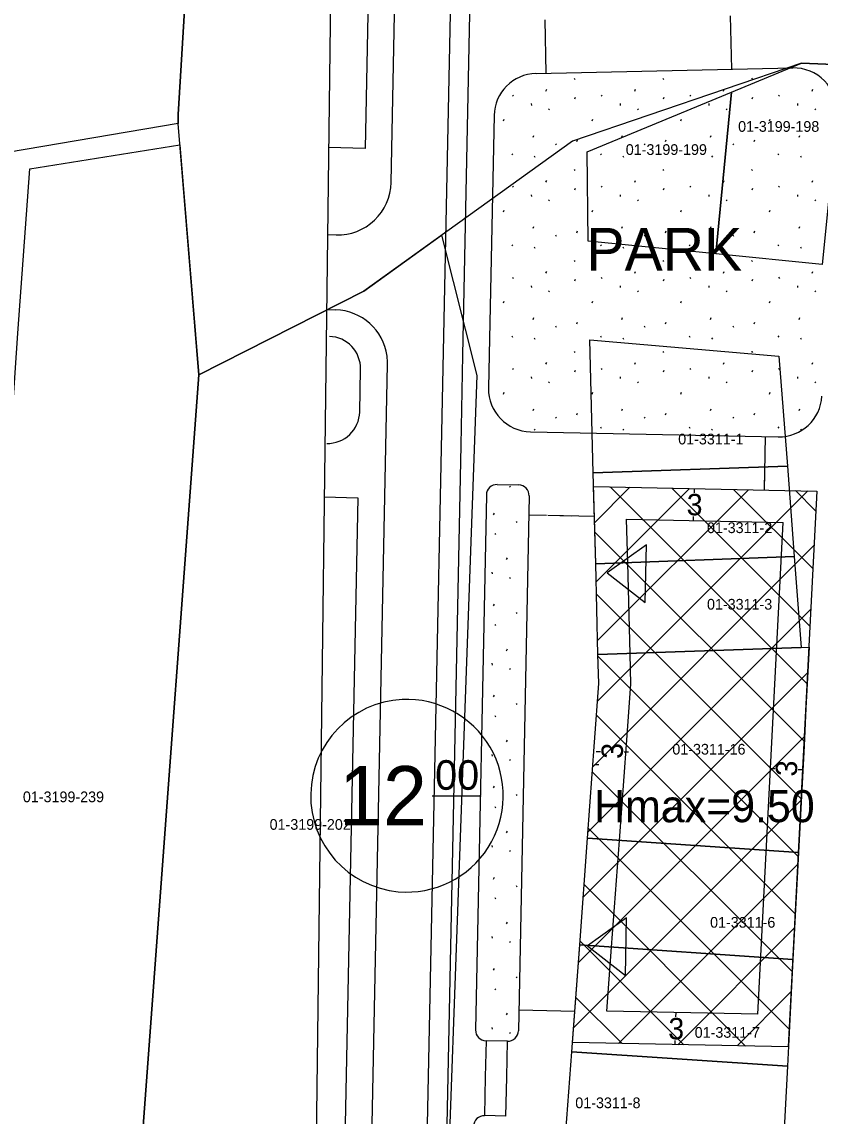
# Model space of a CAD drawing. Extents: x 419396 to 421519, y 4453567 to 4456767.
# Drawn here: x 420396.5 to 420471.1, y 4454516.9 to 4454619.2 of the extents above; entities that cross this region are included whole.
import ezdxf

# ---------------------------------------------------------------- set-up
doc = ezdxf.new("R2010")
doc.units = 0
for name, color, linetype in [('0_KADASTRO', 7, 'Continuous'), ('Level 16', 7, 'Continuous'), ('Level 20', 7, 'Continuous'), ('Level 28', 7, 'Continuous'), ('Level 29', 7, 'Continuous'), ('Level 30', 7, 'Continuous'), ('Level 34', 7, 'Continuous'), ('Level 41', 7, 'Continuous'), ('Level 58', 7, 'Continuous'), ('Level 61', 7, 'Continuous'), ('Level 62', 7, 'Continuous'), ('Level 9', 7, 'Continuous')]:
    doc.layers.add(name, color=color, linetype=linetype)

msp = doc.modelspace()

# ---------------------------------------------------------------- linework, layer by layer
at = {"layer": '0_KADASTRO'}
for points in [[(420411.11, 4454610.55), (420417.99, 4454723.39), (420418.06, 4454727.12), (420520.79, 4454737.14), (420523.08, 4454624.12), (420522.64, 4454620.22), (420521.58, 4454610.83), (420521.56, 4454610.63), (420521.36, 4454610.66), (420513.12, 4454611.66), (420503.2, 4454612.87), (420493.29, 4454614.08), (420489.81, 4454614.5), (420483.17, 4454614.78), (420473.19, 4454615.2), (420469.38, 4454615.35), (420447.99, 4454608.07), (420428.47, 4454594.05), (420413.06, 4454586.21), (420411.13, 4454609.71)], [(420461.37, 4454597.53), (420462.84, 4454612.64), (420469.38, 4454615.35), (420473.19, 4454615.2), (420471.31, 4454596.54)], [(420449.36, 4454607.06), (420462.84, 4454612.64), (420461.37, 4454597.53), (420449.43, 4454598.73)], [(420388.29, 4454473.82), (420396.15, 4454590.13), (420397.27, 4454605.49), (420411.29, 4454607.72), (420413.06, 4454586.21), (420404.4, 4454469.34)], [(420404.4, 4454469.34), (420413.06, 4454586.21), (420428.47, 4454594.05), (420435.75, 4454599.28), (420439.04, 4454586.15), (420434.51, 4454460.97)], [(420449.59, 4454589.48), (420467.28, 4454587.96), (420468.07, 4454577.69), (420449.92, 4454577.07)], [(420449.92, 4454577.07), (420468.07, 4454577.69), (420468.71, 4454569.23), (420450.15, 4454568.56)], [(420450.15, 4454568.56), (420468.71, 4454569.23), (420469.36, 4454560.75), (420450.36, 4454560.07)], [(420449.37, 4454542.91), (420450.04, 4454551.88), (420450.44, 4454557.37), (420450.36, 4454560.07), (420469.36, 4454560.75), (420470.09, 4454560.77), (420469.8, 4454555.06), (420469.63, 4454551.56), (420469.1, 4454541.58)], [(420448.65, 4454532.94), (420449.37, 4454542.91), (420469.1, 4454541.58), (420468.58, 4454531.59)], [(420447.92, 4454522.96), (420448.65, 4454532.94), (420468.58, 4454531.59), (420468.06, 4454521.61)], [(420447.18, 4454512.99), (420447.92, 4454522.96), (420468.06, 4454521.61), (420467.54, 4454511.62)]]:
    msp.add_lwpolyline(points, close=True, dxfattribs=at)
msp.add_lwpolyline([(420372.18, 4454711.5), (420417.99, 4454723.39), (420411.11, 4454610.55), (420411.13, 4454609.71), (420384.14, 4454605.13)], dxfattribs=at)
at = {"layer": 'Level 16'}
for p, q in [((420454.89, 4454570.34), (420451.23, 4454567.72)), ((420454.89, 4454570.34), (420451.23, 4454567.72)), ((420454.78, 4454564.94), (420454.89, 4454570.34)), ((420454.78, 4454564.94), (420454.89, 4454570.34)), ((420451.23, 4454567.72), (420454.78, 4454564.94)), ((420451.23, 4454567.72), (420454.78, 4454564.94)), ((420453.04, 4454535.47), (420449.39, 4454532.84)), ((420453.04, 4454535.47), (420449.39, 4454532.84)), ((420452.94, 4454530.07), (420453.04, 4454535.47)), ((420452.94, 4454530.07), (420453.04, 4454535.47)), ((420449.39, 4454532.84), (420452.94, 4454530.07)), ((420449.39, 4454532.84), (420452.94, 4454530.07))]:
    msp.add_line(p, q, dxfattribs=at)
at = {"layer": 'Level 20'}
for p, q in [((420459.34, 4454575.59), (420459.34, 4454575.19)), ((420459.34, 4454575.59), (420459.34, 4454575.19)), ((420459.34, 4454575.59), (420459.34, 4454575.19)), ((420459.34, 4454575.59), (420459.34, 4454575.19)), ((420453.03, 4454572.72), (420467.67, 4454572.42)), ((420453.14, 4454568.64), (420453.03, 4454572.72)), ((420459.28, 4454572.59), (420459.29, 4454572.99)), ((420459.28, 4454572.59), (420459.29, 4454572.99)), ((420459.28, 4454572.59), (420459.29, 4454572.99)), ((420459.28, 4454572.59), (420459.29, 4454572.99)), ((420465.29, 4454526.46), (420467.67, 4454572.42)), ((420465.29, 4454526.46), (420467.67, 4454572.42)), ((420465.29, 4454526.46), (420467.67, 4454572.42)), ((420465.29, 4454526.46), (420467.67, 4454572.42)), ((420453.36, 4454560.15), (420453.14, 4454568.64)), ((420453.44, 4454557.3), (420453.36, 4454560.15)), ((420453.03, 4454551.66), (420453.44, 4454557.3)), ((420452.36, 4454542.69), (420453.03, 4454551.66)), ((420450.2, 4454551.02), (420450.6, 4454551.01)), ((420450.2, 4454551.02), (420450.6, 4454551.01)), ((420453.2, 4454550.96), (420452.8, 4454550.97)), ((420453.2, 4454550.96), (420452.8, 4454550.97)), ((420450.43, 4454549.77), (420450.03, 4454549.77)), ((420450.43, 4454549.77), (420450.03, 4454549.77)), ((420466.48, 4454549.44), (420466.88, 4454549.42)), ((420466.48, 4454549.44), (420466.88, 4454549.42)), ((420466.48, 4454549.44), (420466.88, 4454549.42)), ((420466.48, 4454549.44), (420466.88, 4454549.42)), ((420469.48, 4454549.29), (420469.08, 4454549.31)), ((420469.48, 4454549.29), (420469.08, 4454549.31)), ((420469.48, 4454549.29), (420469.08, 4454549.31)), ((420469.48, 4454549.29), (420469.08, 4454549.31)), ((420451.64, 4454532.72), (420452.36, 4454542.69)), ((420451.2, 4454526.75), (420451.64, 4454532.72)), ((420465.29, 4454526.46), (420451.2, 4454526.75)), ((420457.63, 4454526.62), (420457.62, 4454526.22)), ((420457.63, 4454526.62), (420457.62, 4454526.22)), ((420457.63, 4454526.62), (420457.62, 4454526.22)), ((420457.63, 4454526.62), (420457.62, 4454526.22)), ((420457.57, 4454523.62), (420457.58, 4454524.02)), ((420457.57, 4454523.62), (420457.58, 4454524.02)), ((420457.57, 4454523.62), (420457.58, 4454524.02)), ((420457.57, 4454523.62), (420457.58, 4454524.02))]:
    msp.add_line(p, q, dxfattribs=at)
at = {"layer": 'Level 28'}
for p, q in [((420445.53, 4454614.41), (420445.42, 4454619.41)), ((420462.73, 4454619.78), (420462.84, 4454614.78)), ((420444.57, 4454614.39), (420468.58, 4454614.91)), ((420440.65, 4454610.47), (420440.2, 4454588.11)), ((420428.59, 4454607.38), (420425.17, 4454607.48)), ((420440.2, 4454588.11), (420440.14, 4454584.98)), ((420428.09, 4454582.75), (420428.17, 4454586.75)), ((420444.06, 4454580.9), (420467.21, 4454580.43)), ((420466, 4454580.46), (420465.9, 4454575.45)), ((420449.88, 4454577.87), (420449.88, 4454577.92)), ((420465.94, 4454577.35), (420465.9, 4454575.45)), ((420440.95, 4454575.97), (420442.95, 4454575.93)), ((420440.95, 4454575.97), (420442.95, 4454575.93)), ((420424.77, 4454574.82), (420427.93, 4454574.73)), ((420439.93, 4454574.99), (420438.92, 4454525)), ((420439.93, 4454574.99), (420438.92, 4454525)), ((420443.93, 4454574.91), (420442.92, 4454524.92)), ((420443.93, 4454574.91), (420442.92, 4454524.92)), ((420443.9, 4454573.14), (420445.54, 4454573.11)), ((420445.67, 4454573.11), (420450.03, 4454573.02)), ((420445.67, 4454573.11), (420447.9, 4454573.06)), ((420442.96, 4454526.87), (420448.2, 4454526.76)), ((420439.9, 4454523.98), (420439.83, 4454520.61)), ((420439.9, 4454523.98), (420439.83, 4454520.61)), ((420441.9, 4454523.94), (420439.9, 4454523.98)), ((420441.9, 4454523.94), (420439.9, 4454523.98)), ((420441.83, 4454520.59), (420441.9, 4454523.94)), ((420441.83, 4454520.59), (420441.9, 4454523.94)), ((420439.83, 4454520.61), (420439.76, 4454516.98)), ((420439.83, 4454520.61), (420439.76, 4454516.98)), ((420441.76, 4454516.94), (420441.83, 4454520.59)), ((420441.76, 4454516.94), (420441.83, 4454520.59)), ((420441.76, 4454516.94), (420439.76, 4454516.98)), ((420441.76, 4454516.94), (420439.76, 4454516.98))]:
    msp.add_line(p, q, dxfattribs=at)
for centre, radius, start, end in [((420444.65, 4454610.39), 4, 91.2212, 178.8411), ((420468.66, 4454610.91), 4, 357.0363, 91.2212), ((420425.17, 4454586.81), 3, 358.8411, 88.3597), ((420444.13, 4454584.9), 4, 178.8411, 268.8411), ((420467.29, 4454584.43), 4, 268.8411, 357.0363), ((420425.09, 4454582.81), 3, 268.3597, 358.8411), ((420440.93, 4454574.97), 1, 88.8411, 178.8411), ((420440.93, 4454574.97), 1, 88.8411, 178.8411), ((420442.93, 4454574.93), 1, 358.8411, 88.8411), ((420442.93, 4454574.93), 1, 358.8411, 88.8411), ((420439.92, 4454524.98), 1, 178.8411, 268.8411), ((420439.92, 4454524.98), 1, 178.8411, 268.8411), ((420441.92, 4454524.94), 1, 268.8411, 358.8411), ((420441.92, 4454524.94), 1, 268.8411, 358.8411), ((420439.74, 4454515.98), 1, 88.8411, 178.8411), ((420439.74, 4454515.98), 1, 88.8411, 178.8411)]:
    msp.add_arc(centre, radius, start, end, dxfattribs=at)
at = {"layer": 'Level 29'}
for p, q in [((420430.79, 4454716.09), (420428.59, 4454607.38)), ((420449.95, 4454575.78), (420470.83, 4454575.36)), ((420450.15, 4454568.56), (420449.95, 4454575.78)), ((420470.83, 4454575.36), (420468.14, 4454523.4)), ((420470.83, 4454575.36), (420468.14, 4454523.4)), ((420427.92, 4454574.73), (420425.83, 4454471.25)), ((420450.36, 4454560.07), (420450.15, 4454568.56)), ((420450.44, 4454557.37), (420450.36, 4454560.07)), ((420450.04, 4454551.88), (420450.44, 4454557.37)), ((420449.37, 4454542.91), (420450.04, 4454551.88)), ((420448.65, 4454532.94), (420449.37, 4454542.91)), ((420447.98, 4454523.81), (420448.65, 4454532.94)), ((420468.14, 4454523.4), (420447.98, 4454523.81))]:
    msp.add_line(p, q, dxfattribs=at)
at = {"layer": 'Level 34'}
for p, q in [((420450.04, 4454572.4), (420453.35, 4454575.71)), ((420450.19, 4454566.89), (420458.9, 4454575.6)), ((420450.32, 4454555.71), (420469.98, 4454575.38)), ((420450.33, 4454561.38), (420464.44, 4454575.49)), ((420469.9, 4454557.35), (420451.49, 4454575.75)), ((420470.17, 4454562.73), (420457.27, 4454575.63)), ((420470.45, 4454568.11), (420463.04, 4454575.52)), ((420470.73, 4454573.48), (420468.81, 4454575.4)), ((420469.62, 4454551.97), (420450.07, 4454571.52)), ((420449.87, 4454549.6), (420470.57, 4454570.3)), ((420469.34, 4454546.59), (420450.22, 4454565.71)), ((420449.42, 4454543.49), (420470.26, 4454564.33)), ((420469.06, 4454541.21), (420450.37, 4454559.9)), ((420448.97, 4454537.39), (420469.95, 4454558.37)), ((420468.78, 4454535.83), (420450.22, 4454554.4)), ((420448.53, 4454531.29), (420469.64, 4454552.4)), ((420468.5, 4454530.46), (420449.83, 4454549.12)), ((420448.08, 4454525.19), (420469.33, 4454546.44)), ((420468.22, 4454525.08), (420449.44, 4454543.86)), ((420452.27, 4454523.72), (420469.02, 4454540.47)), ((420464.16, 4454523.48), (420449.06, 4454538.59)), ((420457.82, 4454523.61), (420468.71, 4454534.5)), ((420458.39, 4454523.6), (420448.67, 4454533.31)), ((420452.61, 4454523.71), (420448.29, 4454528.04)), ((420463.36, 4454523.5), (420468.4, 4454528.54))]:
    msp.add_line(p, q, dxfattribs=at)
at = {"layer": 'Level 41'}
for p, q in [((420448.14, 4454613.94), (420448.21, 4454613.83)), ((420456.43, 4454613.94), (420456.5, 4454613.83)), ((420464.72, 4454613.94), (420464.79, 4454613.83)), ((420442.37, 4454612.36), (420442.44, 4454612.26)), ((420445.49, 4454612.75), (420445.57, 4454612.91)), ((420448.19, 4454612.02), (420448.27, 4454612.18)), ((420450.66, 4454612.36), (420450.73, 4454612.26)), ((420453.79, 4454612.75), (420453.86, 4454612.91)), ((420456.49, 4454612.02), (420456.56, 4454612.18)), ((420458.95, 4454612.36), (420459.02, 4454612.26)), ((420462.08, 4454612.75), (420462.15, 4454612.91)), ((420464.78, 4454612.02), (420464.85, 4454612.18)), ((420467.24, 4454612.36), (420467.32, 4454612.26)), ((420470.37, 4454612.75), (420470.44, 4454612.91)), ((420444.12, 4454611.57), (420444.14, 4454611.41)), ((420445.75, 4454611.1), (420445.82, 4454611)), ((420452.42, 4454611.57), (420452.43, 4454611.41)), ((420454.05, 4454611.1), (420454.12, 4454611)), ((420460.71, 4454611.57), (420460.73, 4454611.41)), ((420462.34, 4454611.1), (420462.41, 4454611)), ((420469, 4454611.57), (420469.02, 4454611.41)), ((420470.63, 4454611.1), (420470.7, 4454611)), ((420441.52, 4454609.96), (420441.59, 4454610.12)), ((420449.81, 4454609.96), (420449.88, 4454610.12)), ((420458.1, 4454609.96), (420458.17, 4454610.12)), ((420466.4, 4454609.96), (420466.47, 4454610.12)), ((420444.29, 4454608.43), (420444.36, 4454608.59)), ((420448.37, 4454608.02), (420448.44, 4454608.18)), ((420452.58, 4454608.43), (420452.65, 4454608.59)), ((420456.66, 4454608.02), (420456.74, 4454608.18)), ((420460.87, 4454608.43), (420460.94, 4454608.59)), ((420464.96, 4454608.02), (420465.03, 4454608.18)), ((420469.17, 4454608.43), (420469.24, 4454608.59)), ((420442.3, 4454606.88), (420442.37, 4454606.78)), ((420446.38, 4454607.81), (420446.45, 4454607.71)), ((420450.59, 4454606.88), (420450.66, 4454606.78)), ((420454.68, 4454607.81), (420454.75, 4454607.71)), ((420458.88, 4454606.88), (420458.96, 4454606.78)), ((420462.97, 4454607.81), (420463.04, 4454607.71)), ((420467.18, 4454606.88), (420467.25, 4454606.78)), ((420444.4, 4454606.69), (420444.47, 4454606.58)), ((420452.69, 4454606.69), (420452.76, 4454606.58)), ((420460.98, 4454606.69), (420461.05, 4454606.58)), ((420469.28, 4454606.69), (420469.35, 4454606.58)), ((420448.14, 4454605.43), (420448.21, 4454605.32)), ((420456.43, 4454605.43), (420456.5, 4454605.32)), ((420464.72, 4454605.43), (420464.79, 4454605.32)), ((420442.37, 4454603.85), (420442.44, 4454603.75)), ((420445.49, 4454604.24), (420445.57, 4454604.4)), ((420450.66, 4454603.85), (420450.73, 4454603.75)), ((420453.79, 4454604.24), (420453.86, 4454604.4)), ((420458.95, 4454603.85), (420459.02, 4454603.75)), ((420462.08, 4454604.24), (420462.15, 4454604.4)), ((420467.24, 4454603.85), (420467.32, 4454603.75)), ((420470.37, 4454604.24), (420470.44, 4454604.4)), ((420444.12, 4454603.06), (420444.14, 4454602.9)), ((420448.19, 4454603.51), (420448.27, 4454603.67)), ((420452.42, 4454603.06), (420452.43, 4454602.9)), ((420456.49, 4454603.51), (420456.56, 4454603.67)), ((420460.71, 4454603.06), (420460.73, 4454602.9)), ((420464.78, 4454603.51), (420464.85, 4454603.67)), ((420469, 4454603.06), (420469.02, 4454602.9)), ((420445.75, 4454602.59), (420445.82, 4454602.49)), ((420454.05, 4454602.59), (420454.12, 4454602.49)), ((420462.34, 4454602.59), (420462.41, 4454602.49)), ((420470.63, 4454602.59), (420470.7, 4454602.49)), ((420441.52, 4454601.45), (420441.59, 4454601.61)), ((420449.81, 4454601.45), (420449.88, 4454601.61)), ((420458.1, 4454601.45), (420458.17, 4454601.61)), ((420466.4, 4454601.45), (420466.47, 4454601.61)), ((420444.29, 4454599.92), (420444.36, 4454600.08)), ((420448.37, 4454599.51), (420448.44, 4454599.67)), ((420452.58, 4454599.92), (420452.65, 4454600.08)), ((420456.66, 4454599.51), (420456.74, 4454599.67)), ((420460.87, 4454599.92), (420460.94, 4454600.08)), ((420464.96, 4454599.51), (420465.03, 4454599.67)), ((420469.17, 4454599.92), (420469.24, 4454600.08)), ((420446.38, 4454599.3), (420446.45, 4454599.2)), ((420454.68, 4454599.3), (420454.75, 4454599.2)), ((420462.97, 4454599.3), (420463.04, 4454599.2)), ((420442.3, 4454598.37), (420442.37, 4454598.27)), ((420444.4, 4454598.18), (420444.47, 4454598.07)), ((420450.59, 4454598.37), (420450.66, 4454598.27)), ((420452.69, 4454598.18), (420452.76, 4454598.07)), ((420458.88, 4454598.37), (420458.96, 4454598.27)), ((420460.98, 4454598.18), (420461.05, 4454598.07)), ((420467.18, 4454598.37), (420467.25, 4454598.27)), ((420469.28, 4454598.18), (420469.35, 4454598.07)), ((420448.14, 4454596.92), (420448.21, 4454596.81)), ((420456.43, 4454596.92), (420456.5, 4454596.81)), ((420464.72, 4454596.92), (420464.79, 4454596.81)), ((420445.49, 4454595.73), (420445.57, 4454595.89)), ((420453.79, 4454595.73), (420453.86, 4454595.89)), ((420462.08, 4454595.73), (420462.15, 4454595.89)), ((420470.37, 4454595.73), (420470.44, 4454595.89)), ((420442.37, 4454595.34), (420442.44, 4454595.24)), ((420444.12, 4454594.55), (420444.14, 4454594.39)), ((420448.19, 4454595), (420448.27, 4454595.16)), ((420450.66, 4454595.34), (420450.73, 4454595.24)), ((420452.42, 4454594.55), (420452.43, 4454594.39)), ((420456.49, 4454595), (420456.56, 4454595.16)), ((420458.95, 4454595.34), (420459.02, 4454595.24)), ((420460.71, 4454594.55), (420460.73, 4454594.39)), ((420464.78, 4454595), (420464.85, 4454595.16)), ((420467.24, 4454595.34), (420467.32, 4454595.24)), ((420469, 4454594.55), (420469.02, 4454594.39)), ((420445.75, 4454594.08), (420445.82, 4454593.98)), ((420454.05, 4454594.08), (420454.12, 4454593.98)), ((420462.34, 4454594.08), (420462.41, 4454593.98)), ((420470.63, 4454594.08), (420470.7, 4454593.98)), ((420441.52, 4454592.94), (420441.59, 4454593.1)), ((420449.81, 4454592.94), (420449.88, 4454593.1)), ((420458.1, 4454592.94), (420458.17, 4454593.1)), ((420466.4, 4454592.94), (420466.47, 4454593.1)), ((420444.29, 4454591.41), (420444.36, 4454591.57)), ((420452.58, 4454591.41), (420452.65, 4454591.57)), ((420460.87, 4454591.41), (420460.94, 4454591.57)), ((420469.17, 4454591.41), (420469.24, 4454591.57)), ((420446.38, 4454590.79), (420446.45, 4454590.69)), ((420448.37, 4454591), (420448.44, 4454591.16)), ((420454.68, 4454590.79), (420454.75, 4454590.69)), ((420456.66, 4454591), (420456.74, 4454591.16)), ((420462.97, 4454590.79), (420463.04, 4454590.69)), ((420464.96, 4454591), (420465.03, 4454591.16)), ((420442.3, 4454589.86), (420442.37, 4454589.76)), ((420444.4, 4454589.67), (420444.47, 4454589.56)), ((420450.59, 4454589.86), (420450.66, 4454589.76)), ((420452.69, 4454589.67), (420452.76, 4454589.56)), ((420458.88, 4454589.86), (420458.96, 4454589.76)), ((420460.98, 4454589.67), (420461.05, 4454589.56)), ((420467.18, 4454589.86), (420467.25, 4454589.76)), ((420469.28, 4454589.67), (420469.35, 4454589.56)), ((420448.14, 4454588.41), (420448.21, 4454588.3)), ((420456.43, 4454588.41), (420456.5, 4454588.3)), ((420464.72, 4454588.41), (420464.73, 4454588.41)), ((420464.73, 4454588.41), (420464.79, 4454588.3)), ((420445.49, 4454587.22), (420445.57, 4454587.38)), ((420453.79, 4454587.22), (420453.86, 4454587.38)), ((420456.5, 4454588.3), (420456.5, 4454588.3)), ((420462.08, 4454587.22), (420462.15, 4454587.38)), ((420470.37, 4454587.22), (420470.44, 4454587.38)), ((420442.37, 4454586.83), (420442.44, 4454586.73)), ((420448.19, 4454586.49), (420448.27, 4454586.65)), ((420450.66, 4454586.83), (420450.73, 4454586.73)), ((420456.49, 4454586.49), (420456.56, 4454586.65)), ((420458.95, 4454586.83), (420459.02, 4454586.73)), ((420464.78, 4454586.49), (420464.85, 4454586.65)), ((420467.24, 4454586.83), (420467.32, 4454586.73)), ((420444.12, 4454586.04), (420444.14, 4454585.88)), ((420445.75, 4454585.57), (420445.82, 4454585.47)), ((420452.42, 4454586.04), (420452.43, 4454585.88)), ((420454.05, 4454585.57), (420454.12, 4454585.47)), ((420460.71, 4454586.04), (420460.73, 4454585.88)), ((420462.34, 4454585.57), (420462.41, 4454585.47)), ((420469, 4454586.04), (420469.02, 4454585.88)), ((420470.63, 4454585.57), (420470.7, 4454585.47)), ((420441.52, 4454584.43), (420441.59, 4454584.59)), ((420449.81, 4454584.43), (420449.88, 4454584.59)), ((420458.1, 4454584.43), (420458.17, 4454584.59)), ((420466.4, 4454584.43), (420466.47, 4454584.59)), ((420444.29, 4454582.9), (420444.36, 4454583.06)), ((420446.38, 4454582.28), (420446.45, 4454582.18)), ((420448.37, 4454582.49), (420448.44, 4454582.65)), ((420452.58, 4454582.9), (420452.65, 4454583.06)), ((420454.68, 4454582.28), (420454.75, 4454582.18)), ((420456.66, 4454582.49), (420456.74, 4454582.65)), ((420460.87, 4454582.9), (420460.94, 4454583.06)), ((420462.97, 4454582.28), (420463.04, 4454582.18)), ((420464.96, 4454582.49), (420465.03, 4454582.65)), ((420469.17, 4454582.9), (420469.24, 4454583.06)), ((420450.59, 4454581.35), (420450.66, 4454581.25)), ((420458.88, 4454581.35), (420458.96, 4454581.25)), ((420467.18, 4454581.35), (420467.25, 4454581.25)), ((420444.4, 4454581.16), (420444.47, 4454581.05)), ((420452.69, 4454581.16), (420452.76, 4454581.05)), ((420460.98, 4454581.16), (420461.05, 4454581.05)), ((420469.28, 4454581.16), (420469.35, 4454581.05)), ((420442.08, 4454575.81), (420442.15, 4454575.71)), ((420440.61, 4454573.14), (420440.68, 4454573.3)), ((420442.71, 4454572.52), (420442.78, 4454572.42)), ((420440.72, 4454571.4), (420440.79, 4454571.29)), ((420441.82, 4454568.95), (420441.89, 4454569.11)), ((420440.45, 4454567.77), (420440.47, 4454567.61)), ((420442.08, 4454567.3), (420442.15, 4454567.2)), ((420440.61, 4454564.63), (420440.68, 4454564.79)), ((420442.71, 4454564.01), (420442.78, 4454563.91)), ((420440.72, 4454562.89), (420440.79, 4454562.78)), ((420441.82, 4454560.44), (420441.89, 4454560.6)), ((420440.45, 4454559.26), (420440.47, 4454559.1)), ((420442.08, 4454558.79), (420442.15, 4454558.69)), ((420440.61, 4454556.12), (420440.68, 4454556.28)), ((420442.71, 4454555.5), (420442.78, 4454555.4)), ((420440.72, 4454554.38), (420440.79, 4454554.27)), ((420441.82, 4454551.93), (420441.89, 4454552.09)), ((420440.45, 4454550.75), (420440.47, 4454550.59)), ((420442.08, 4454550.28), (420442.15, 4454550.18)), ((420440.61, 4454547.61), (420440.68, 4454547.77)), ((420442.71, 4454546.99), (420442.78, 4454546.89)), ((420440.72, 4454545.87), (420440.79, 4454545.76)), ((420441.82, 4454543.42), (420441.89, 4454543.58)), ((420440.45, 4454542.24), (420440.47, 4454542.08)), ((420442.08, 4454541.77), (420442.15, 4454541.67)), ((420440.61, 4454539.1), (420440.68, 4454539.26)), ((420442.71, 4454538.48), (420442.78, 4454538.38)), ((420440.72, 4454537.36), (420440.79, 4454537.25)), ((420441.82, 4454534.91), (420441.89, 4454535.07)), ((420440.45, 4454533.73), (420440.47, 4454533.57)), ((420442.08, 4454533.26), (420442.15, 4454533.16)), ((420440.61, 4454530.59), (420440.68, 4454530.75)), ((420442.71, 4454529.97), (420442.78, 4454529.87)), ((420440.72, 4454528.85), (420440.79, 4454528.74)), ((420441.82, 4454526.4), (420441.89, 4454526.56)), ((420440.45, 4454525.22), (420440.47, 4454525.06)), ((420442.08, 4454524.75), (420442.15, 4454524.65))]:
    msp.add_line(p, q, dxfattribs=at)
at = {"layer": 'Level 58'}
msp.add_line((420434.87, 4454546.88), (420439.43, 4454546.88), dxfattribs=at)
for start, end in [(92.9338, 264.8282), (264.8282, 92.9338)]:
    msp.add_arc((420432.51, 4454546.88), 9, start, end, dxfattribs=at)
at = {"layer": 'Level 62'}
for p, q in [((420440.37, 4454719.97), (420437.7, 4454588.07)), ((420431.03, 4454604.2), (420433.34, 4454718.26)), ((420425.07, 4454599.33), (420425.89, 4454599.3)), ((420424.99, 4454592.33), (420425.83, 4454592.3)), ((420437.7, 4454588.07), (420437.53, 4454579.66)), ((420437.7, 4454588.07), (420437.7, 4454588.07)), ((420429.18, 4454512.81), (420430.68, 4454587.2)), ((420429.18, 4454512.81), (420430.68, 4454587.2)), ((420437.53, 4454579.66), (420436.34, 4454520.66)), ((420436.34, 4454520.66), (420436.18, 4454512.81))]:
    msp.add_line(p, q, dxfattribs=at)
for centre, start, end in [((420426.03, 4454604.3), 268.3698, 358.8411), ((420425.69, 4454587.3), 7.8603, 88.3597), ((420425.69, 4454587.3), 358.8411, 7.8603)]:
    msp.add_arc(centre, 5, start, end, dxfattribs=at)
at = {"layer": 'Level 9'}
for p, q in [((420432.76, 4454436.23), (420438.68, 4454721.11)), ((420426.53, 4454716.81), (420423.29, 4454455.37))]:
    msp.add_line(p, q, dxfattribs=at)

# ---------------------------------------------------------------- texts
at = {"layer": '0_KADASTRO'}
for s, p in [('01-3199-198', (420463.46, 4454608.94)), ('01-3199-199', (420452.96, 4454606.78)), ('01-3311-1', (420457.86, 4454579.72)), ('01-3311-2', (420460.55, 4454571.43)), ('01-3311-3', (420460.55, 4454564.28)), ('01-3311-16', (420457.31, 4454550.73)), ('01-3199-239', (420396.61, 4454546.28)), ('01-3199-202', (420419.67, 4454543.7)), ('01-3311-6', (420460.84, 4454534.55)), ('01-3311-7', (420459.4, 4454524.26)), ('01-3311-8', (420448.24, 4454517.68))]:
    msp.add_text(s, height=1, dxfattribs=at).set_placement(p)
at = {"layer": 'Level 20'}
for rotation, p in [(358.8411, (420458.63, 4454573.11)), (358.8411, (420458.63, 4454573.11)), (358.8411, (420458.63, 4454573.11)), (358.8411, (420458.63, 4454573.11)), (88.8411, (420452.68, 4454550.31)), (88.8411, (420452.68, 4454550.31)), (87.0363, (420468.94, 4454548.65)), (87.0363, (420468.94, 4454548.65)), (87.0363, (420468.94, 4454548.65)), (87.0363, (420468.94, 4454548.65)), (358.8411, (420456.91, 4454524.13)), (358.8411, (420456.91, 4454524.13)), (358.8411, (420456.91, 4454524.13)), (358.8411, (420456.91, 4454524.13))]:
    msp.add_text('3', height=2, rotation=rotation, dxfattribs=at).set_placement(p)
at = {"layer": 'Level 30'}
msp.add_text('Hmax=9.50', height=3, dxfattribs=at).set_placement((420449.99, 4454544.41))
at = {"layer": 'Level 58'}
for s, height, p in [('12', 5.534, (420426.15, 4454544.12)), ('00', 2.767, (420435.14, 4454547.44))]:
    msp.add_text(s, height=height, dxfattribs=at).set_placement(p)
at = {"layer": 'Level 61'}
msp.add_text('PARK', height=4, dxfattribs=at).set_placement((420449.28, 4454595.95))

doc.saveas('drawing.dxf')
